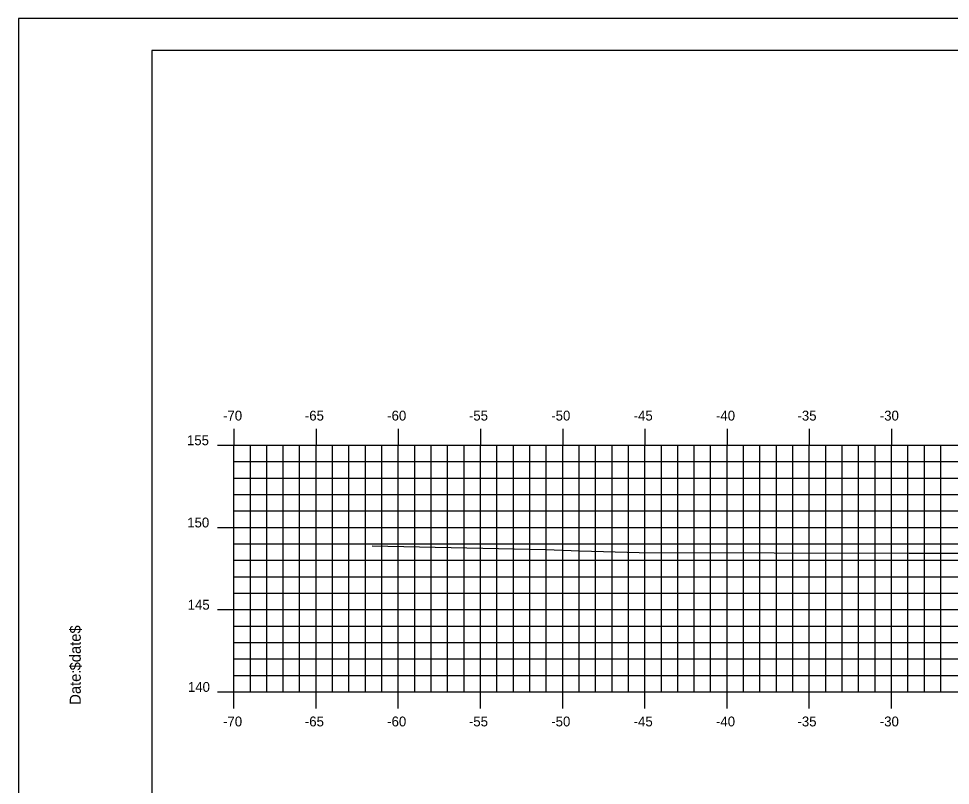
# Model space of a CAD drawing. Extents: x 1147855 to 1148025, y 608981 to 609091.
# Drawn here: x 1147855.1 to 1147911.8, y 609044.6 to 609091.3 of the extents above; entities that cross this region are included whole.
import ezdxf

# ---------------------------------------------------------------- set-up
doc = ezdxf.new("R2010")
doc.units = 0
for name, color, linetype in [('BORDER', 7, 'Continuous'), ('H_V ANNOTATION', 7, 'Continuous'), ('MAJOR', 7, 'Continuous'), ('MINOR', 7, 'Continuous'), ('PLOT BOUNDARY', 7, 'Continuous'), ('S_Roadway_Centerline', 7, 'Continuous')]:
    doc.layers.add(name, color=color, linetype=linetype)

msp = doc.modelspace()

# ---------------------------------------------------------------- linework, layer by layer
at = {"layer": 'BORDER'}
msp.add_lwpolyline([(1147863.211, 608984.335), (1148023.211, 608984.335), (1148023.211, 609089.335), (1147863.211, 609089.335)], close=True, dxfattribs=at)
at = {"layer": 'MAJOR'}
for p, q in [((1147868.211, 609066.337), (1147868.211, 609065.335)), ((1147873.211, 609066.337), (1147873.211, 609065.335)), ((1147878.211, 609066.337), (1147878.211, 609065.335)), ((1147883.211, 609066.337), (1147883.211, 609065.335)), ((1147888.211, 609066.337), (1147888.211, 609065.335)), ((1147893.211, 609066.337), (1147893.211, 609065.335)), ((1147898.211, 609066.337), (1147898.211, 609065.335)), ((1147903.211, 609066.337), (1147903.211, 609065.335)), ((1147908.211, 609066.337), (1147908.211, 609065.335)), ((1147867.209, 609065.335), (1147868.211, 609065.335)), ((1147868.211, 609065.335), (1148008.211, 609065.335)), ((1147868.211, 609050.335), (1147868.211, 609065.335)), ((1147868.211, 609050.335), (1147868.211, 609065.335)), ((1147868.211, 609065.335), (1148008.211, 609065.335)), ((1147873.211, 609050.335), (1147873.211, 609065.335)), ((1147878.211, 609050.335), (1147878.211, 609065.335)), ((1147883.211, 609050.335), (1147883.211, 609065.335)), ((1147888.211, 609050.335), (1147888.211, 609065.335)), ((1147893.211, 609050.335), (1147893.211, 609065.335)), ((1147898.211, 609050.335), (1147898.211, 609065.335)), ((1147903.211, 609050.335), (1147903.211, 609065.335)), ((1147908.211, 609050.335), (1147908.211, 609065.335)), ((1147867.209, 609060.335), (1147868.211, 609060.335)), ((1147868.211, 609060.335), (1148008.211, 609060.335)), ((1147867.209, 609055.335), (1147868.211, 609055.335)), ((1147868.211, 609055.335), (1148008.211, 609055.335)), ((1147867.209, 609050.335), (1147868.211, 609050.335)), ((1147868.211, 609050.335), (1148008.211, 609050.335)), ((1147868.211, 609050.335), (1148008.211, 609050.335)), ((1147868.211, 609049.333), (1147868.211, 609050.335)), ((1147873.211, 609049.333), (1147873.211, 609050.335)), ((1147878.211, 609049.333), (1147878.211, 609050.335)), ((1147883.211, 609049.333), (1147883.211, 609050.335)), ((1147888.211, 609049.333), (1147888.211, 609050.335)), ((1147893.211, 609049.333), (1147893.211, 609050.335)), ((1147898.211, 609049.333), (1147898.211, 609050.335)), ((1147903.211, 609049.333), (1147903.211, 609050.335)), ((1147908.211, 609049.333), (1147908.211, 609050.335))]:
    msp.add_line(p, q, dxfattribs=at)
at = {"layer": 'MINOR'}
for p, q in [((1147869.211, 609050.335), (1147869.211, 609065.335)), ((1147870.211, 609050.335), (1147870.211, 609065.335)), ((1147871.211, 609050.335), (1147871.211, 609065.335)), ((1147872.211, 609050.335), (1147872.211, 609065.335)), ((1147874.211, 609050.335), (1147874.211, 609065.335)), ((1147875.211, 609050.335), (1147875.211, 609065.335)), ((1147876.211, 609050.335), (1147876.211, 609065.335)), ((1147877.211, 609050.335), (1147877.211, 609065.335)), ((1147879.211, 609050.335), (1147879.211, 609065.335)), ((1147880.211, 609050.335), (1147880.211, 609065.335)), ((1147881.211, 609050.335), (1147881.211, 609065.335)), ((1147882.211, 609050.335), (1147882.211, 609065.335)), ((1147884.211, 609050.335), (1147884.211, 609065.335)), ((1147885.211, 609050.335), (1147885.211, 609065.335)), ((1147886.211, 609050.335), (1147886.211, 609065.335)), ((1147887.211, 609050.335), (1147887.211, 609065.335)), ((1147889.211, 609050.335), (1147889.211, 609065.335)), ((1147890.211, 609050.335), (1147890.211, 609065.335)), ((1147891.211, 609050.335), (1147891.211, 609065.335)), ((1147892.211, 609050.335), (1147892.211, 609065.335)), ((1147894.211, 609050.335), (1147894.211, 609065.335)), ((1147895.211, 609050.335), (1147895.211, 609065.335)), ((1147896.211, 609050.335), (1147896.211, 609065.335)), ((1147897.211, 609050.335), (1147897.211, 609065.335)), ((1147899.211, 609050.335), (1147899.211, 609065.335)), ((1147900.211, 609050.335), (1147900.211, 609065.335)), ((1147901.211, 609050.335), (1147901.211, 609065.335)), ((1147902.211, 609050.335), (1147902.211, 609065.335)), ((1147904.211, 609050.335), (1147904.211, 609065.335)), ((1147905.211, 609050.335), (1147905.211, 609065.335)), ((1147906.211, 609050.335), (1147906.211, 609065.335)), ((1147907.211, 609050.335), (1147907.211, 609065.335)), ((1147909.211, 609050.335), (1147909.211, 609065.335)), ((1147910.211, 609050.335), (1147910.211, 609065.335)), ((1147911.211, 609050.335), (1147911.211, 609065.335)), ((1147868.211, 609064.335), (1148008.211, 609064.335)), ((1147868.211, 609064.335), (1147869.213, 609064.335)), ((1147868.211, 609063.335), (1148008.211, 609063.335)), ((1147868.211, 609063.335), (1147869.213, 609063.335)), ((1147868.211, 609062.335), (1148008.211, 609062.335)), ((1147868.211, 609062.335), (1147869.213, 609062.335)), ((1147868.211, 609061.335), (1148008.211, 609061.335)), ((1147868.211, 609061.335), (1147869.213, 609061.335)), ((1147868.211, 609059.335), (1148008.211, 609059.335)), ((1147868.211, 609059.335), (1147869.213, 609059.335)), ((1147868.211, 609058.335), (1148008.211, 609058.335)), ((1147868.211, 609058.335), (1147869.213, 609058.335)), ((1147868.211, 609057.335), (1148008.211, 609057.335)), ((1147868.211, 609057.335), (1147869.213, 609057.335)), ((1147868.211, 609056.335), (1148008.211, 609056.335)), ((1147868.211, 609056.335), (1147869.213, 609056.335)), ((1147868.211, 609054.335), (1148008.211, 609054.335)), ((1147868.211, 609054.335), (1147869.213, 609054.335)), ((1147868.211, 609053.335), (1148008.211, 609053.335)), ((1147868.211, 609053.335), (1147869.213, 609053.335)), ((1147868.211, 609052.335), (1148008.211, 609052.335)), ((1147868.211, 609052.335), (1147869.213, 609052.335)), ((1147868.211, 609051.335), (1148008.211, 609051.335)), ((1147868.211, 609051.335), (1147869.213, 609051.335))]:
    msp.add_line(p, q, dxfattribs=at)
at = {"layer": 'PLOT BOUNDARY'}
msp.add_lwpolyline([(1147855.117, 608981.276), (1148025.117, 608981.276), (1148025.117, 609091.276), (1147855.117, 609091.276)], close=True, dxfattribs=at)
at = {"layer": 'S_Roadway_Centerline'}
msp.add_lwpolyline([(1147876.627, 609059.215), (1147887.18, 609058.993), (1147889.241, 609058.903), (1147892.857, 609058.818), (1147909.277, 609058.762), (1147913.241, 609058.762), (1147913.605, 609058.678), (1147919.446, 609057.084), (1147921.464, 609057.25), (1147923.171, 609057.543), (1147925.188, 609057.705), (1147926.357, 609057.777), (1147928.34, 609057.797), (1147938.457, 609057.934), (1147944.059, 609057.8), (1147958.404, 609057.477), (1147959.911, 609057.57), (1147961.807, 609057.574), (1147963.81, 609057.667), (1147966.876, 609057.692), (1147971.682, 609057.89), (1147974.776, 609057.896), (1147977.299, 609057.854), (1147987.896, 609058.024)], dxfattribs=at)

# ---------------------------------------------------------------- texts
at = {"layer": 'BORDER'}
for s, p in [('$date$', (1147858.896, 609051.64)), ('Date:', (1147858.896, 609049.552))]:
    msp.add_text(s, height=0.6696, rotation=90, dxfattribs=at).set_placement(p)
at = {"layer": 'H_V ANNOTATION'}
for s, p in [('-70', (1147867.552, 609066.835)), ('-65', (1147872.528, 609066.835)), ('-60', (1147877.536, 609066.835)), ('-55', (1147882.507, 609066.835)), ('-50', (1147887.515, 609066.835)), ('-45', (1147892.528, 609066.835)), ('-40', (1147897.536, 609066.835)), ('-35', (1147902.491, 609066.835)), ('-30', (1147907.499, 609066.835)), ('155', (1147865.356, 609065.335)), ('150', (1147865.372, 609060.335)), ('145', (1147865.399, 609055.335)), ('140', (1147865.415, 609050.335)), ('-70', (1147867.552, 609048.235)), ('-65', (1147872.528, 609048.235)), ('-60', (1147877.536, 609048.235)), ('-55', (1147882.507, 609048.235)), ('-50', (1147887.515, 609048.235)), ('-45', (1147892.528, 609048.235)), ('-40', (1147897.536, 609048.235)), ('-35', (1147902.491, 609048.235)), ('-30', (1147907.499, 609048.235))]:
    msp.add_text(s, height=0.6, dxfattribs=at).set_placement(p)
at = {"layer": 'MAJOR'}
msp.add_text('-', height=0.006, dxfattribs=at).set_placement((1147868.206, 609050.335))

doc.saveas('drawing.dxf')
